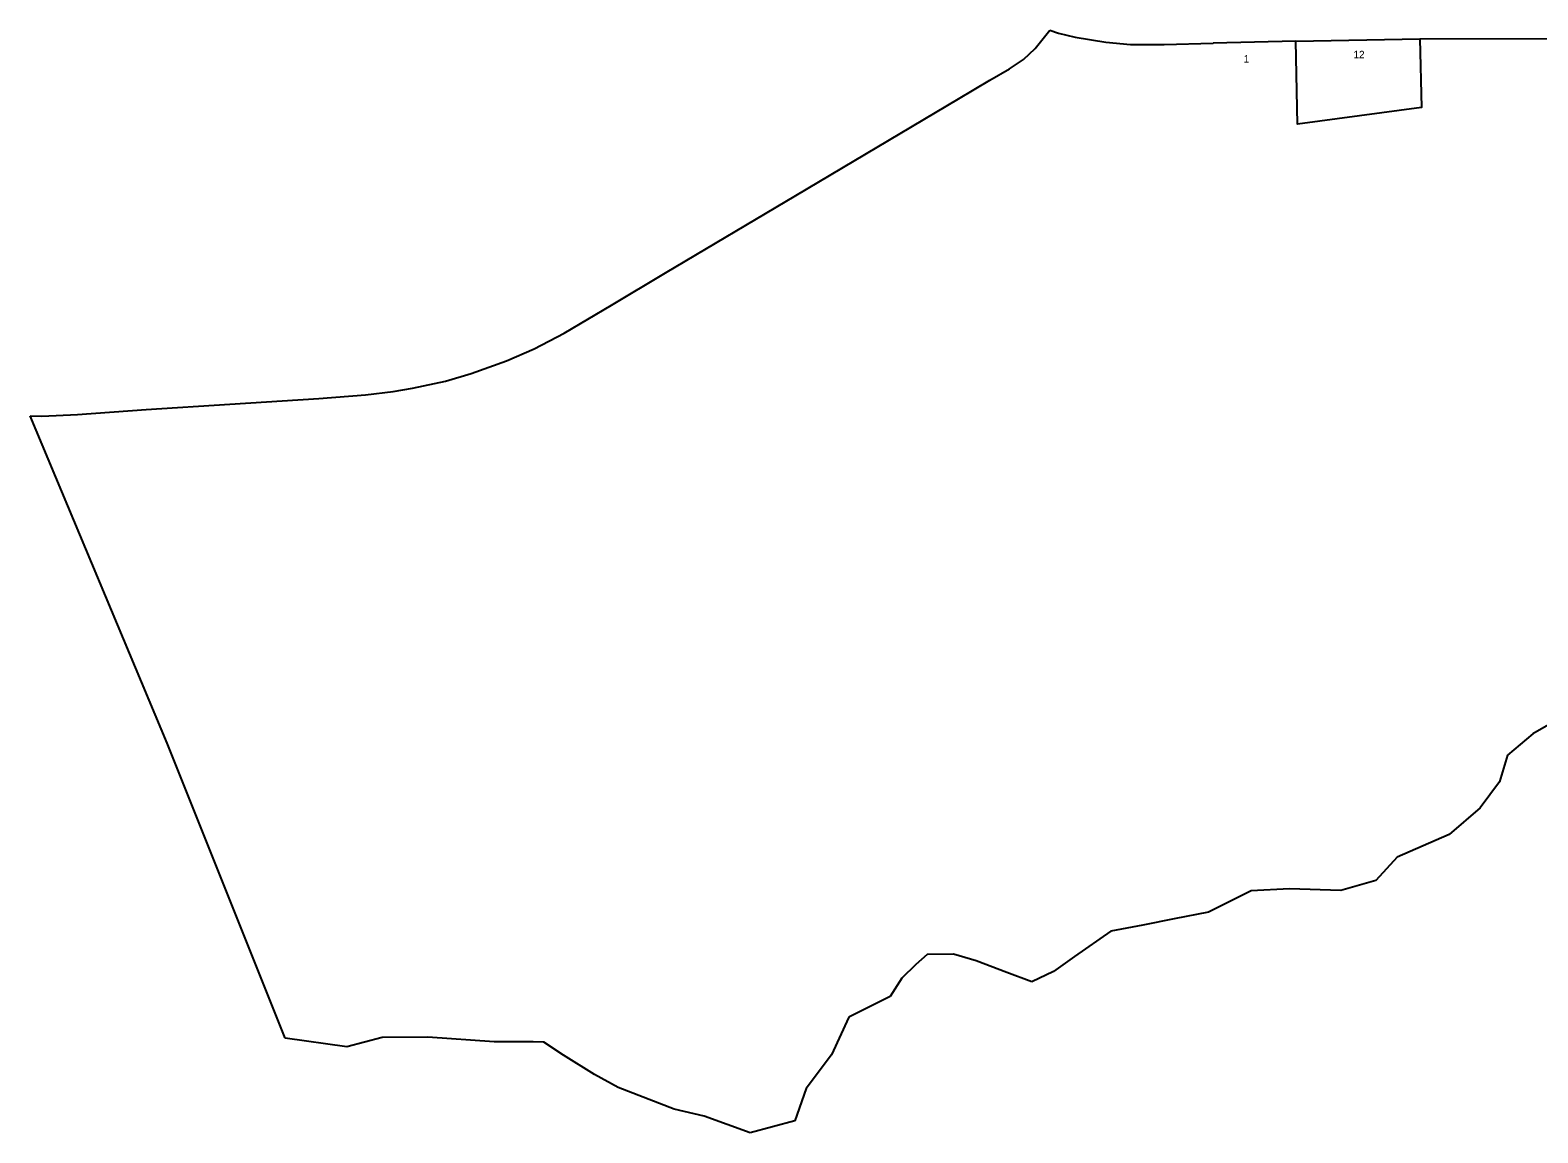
# Model space of a CAD drawing. Extents: x 2526541 to 2533927, y 932914 to 940964.
# Drawn here: x 2526541 to 2530184, y 932914 to 935577 of the extents above; entities that cross this region are included whole.
import ezdxf

# ---------------------------------------------------------------- set-up
doc = ezdxf.new("R2010")
doc.units = 0
doc.layers.add('RD_EX_DV_Prop', color=7, linetype='Continuous')
doc.layers.add('RD_EX_DV_TX_Prop', color=7, linetype='Continuous')

msp = doc.modelspace()

# ---------------------------------------------------------------- linework, layer by layer
at = {"layer": 'RD_EX_DV_Prop'}
for p, q in [((2528969.3, 935532.6), (2529005, 935577.2)), ((2529005, 935577.2), (2529025.9, 935570.1)), ((2529025.9, 935570.1), (2529066.4, 935560.5)), ((2529066.4, 935560.5), (2529140.6, 935547.9)), ((2529599.5, 935550.4), (2529899.5, 935556.6)), ((2529899.5, 935556.6), (2530229.3, 935557.2)), ((2528941, 935506.6), (2528969.3, 935532.6)), ((2529140.6, 935547.9), (2529199.9, 935542.9)), ((2529199.9, 935542.9), (2529281.2, 935542.9)), ((2529599.5, 935550.4), (2529399.6, 935546.2)), ((2528860.3, 935456.5), (2528907.4, 935484)), ((2528907.4, 935484), (2528941, 935506.6)), ((2528784.5, 935411.5), (2528860.3, 935456.5)), ((2528391.3, 935178.1), (2528784.5, 935411.5)), ((2528076.1, 934991), (2528391.3, 935178.1)), ((2527945.3, 934912.6), (2528076.1, 934991)), ((2527830.9, 934845.7), (2527945.3, 934912.6)), ((2527758.9, 934807.6), (2527830.9, 934845.7)), ((2527691.9, 934778.7), (2527758.9, 934807.6)), ((2527606.2, 934747.9), (2527691.9, 934778.7)), ((2527464.8, 934712.3), (2527544.6, 934729.5)), ((2527544.6, 934729.5), (2527606.2, 934747.9)), ((2527023.2, 934673.9), (2527238.5, 934687.5)), ((2527238.5, 934687.5), (2527351.2, 934696.3)), ((2527351.2, 934696.3), (2527417.9, 934704.4)), ((2527417.9, 934704.4), (2527464.8, 934712.3)), ((2526871.8, 933855.3), (2526540.7, 934645.8)), ((2526540.7, 934645.8), (2526569.1, 934644.7)), ((2526569.1, 934644.7), (2526655.1, 934648.8)), ((2526569.1, 934644.7), (2526569.1, 934644.7)), ((2526655.1, 934648.8), (2526821.4, 934660.9)), ((2526821.4, 934660.9), (2527023.2, 934673.9)), ((2530227.3, 933909.3), (2530171.8, 933877.8)), ((2527156.7, 933142.4), (2526871.8, 933855.3)), ((2530171.8, 933877.8), (2530110.7, 933826)), ((2530110.7, 933826), (2530091.3, 933762)), ((2530091.3, 933762), (2530044.7, 933699.2)), ((2530044.7, 933699.2), (2529969.7, 933634.4)), ((2529969.7, 933634.4), (2529844, 933580)), ((2529844, 933580), (2529792.4, 933523.7)), ((2529792.4, 933523.7), (2529707.9, 933499.3)), ((2529491.2, 933498.4), (2529388, 933446.8)), ((2529584.1, 933503.1), (2529491.2, 933498.4)), ((2529707.9, 933499.3), (2529584.1, 933503.1)), ((2529388, 933446.8), (2529305.5, 933430.9)), ((2529229.5, 933415.8), (2529152.6, 933400.8)), ((2529305.5, 933430.9), (2529229.5, 933415.8)), ((2529152.6, 933400.8), (2529064.3, 933339.9)), ((2528708.8, 933344.5), (2528681.5, 933320.1)), ((2528772.5, 933345.5), (2528708.8, 933344.5)), ((2528827, 933329.6), (2528772.5, 933345.5)), ((2529064.3, 933339.9), (2529013.7, 933303.3)), ((2528681.5, 933320.1), (2528646.9, 933287.3)), ((2528901.1, 933301.4), (2528827, 933329.6)), ((2528961.1, 933278.8), (2528901.1, 933301.4)), ((2529013.7, 933303.3), (2528961.1, 933278.8)), ((2528646.9, 933287.3), (2528618.7, 933243.2)), ((2528618.7, 933243.2), (2528575.6, 933221.6)), ((2528519.2, 933193.5), (2528477, 933102.5)), ((2528575.6, 933221.6), (2528519.2, 933193.5)), ((2527306.3, 933121.6), (2527156.7, 933142.4)), ((2527391.7, 933144.1), (2527306.3, 933121.6)), ((2527501.8, 933145.2), (2527391.7, 933144.1)), ((2527662.1, 933133.4), (2527501.8, 933145.2)), ((2527756.1, 933133.4), (2527662.1, 933133.4)), ((2527782.1, 933133.1), (2527756.1, 933133.4)), ((2527829.7, 933101.6), (2527782.1, 933133.1)), ((2527904.7, 933054.6), (2527829.7, 933101.6)), ((2528477, 933102.5), (2528416, 933020.8)), ((2527962, 933023.7), (2527904.7, 933054.6)), ((2528097.1, 932971.1), (2527962, 933023.7)), ((2528416, 933020.8), (2528388.9, 932943)), ((2528169.8, 932954.2), (2528097.1, 932971.1)), ((2528280.9, 932913.9), (2528169.8, 932954.2)), ((2528388.9, 932943), (2528280.9, 932913.9))]:
    msp.add_line(p, q, dxfattribs=at)
for points in [[(2529899.5, 935556.3), (2529902.9, 935390.4), (2529603.7, 935350.4), (2529599.6, 935550.4)], [(2529281.2, 935542.9), (2529281.2, 935542.9), (2529281.2, 935542.9), (2529281.2, 935542.9), (2529399.6, 935546.2), (2529399.6, 935546.2)]]:
    msp.add_lwpolyline(points, dxfattribs=at)

# ---------------------------------------------------------------- texts
at = {"layer": 'RD_EX_DV_TX_Prop'}
for s, p in [('12', (2529738.7, 935509.3)), ('1', (2529473.4, 935498.9))]:
    msp.add_text(s, height=18, dxfattribs=at).set_placement(p)

doc.saveas('drawing.dxf')
